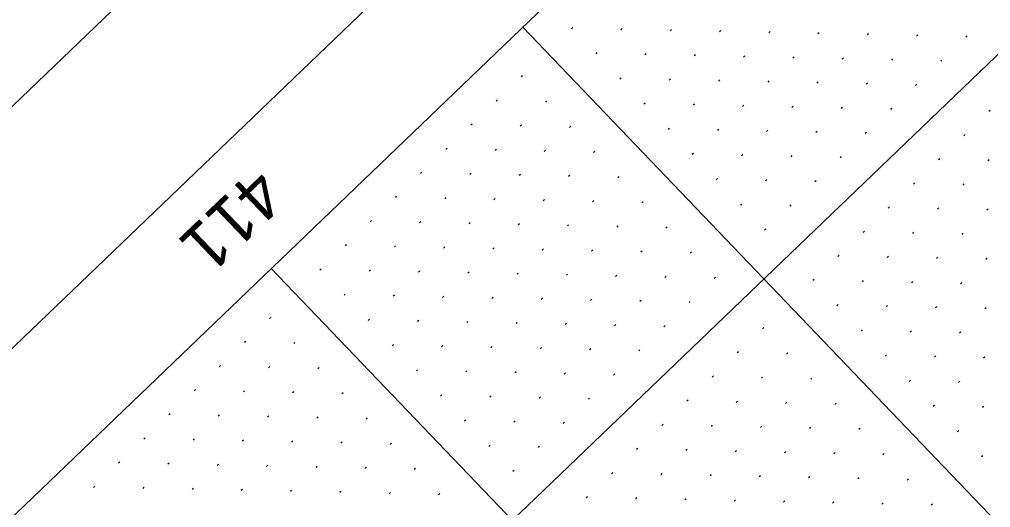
# Model space of a CAD drawing. Extents: x 2148987 to 2151117, y 142806 to 144993.
# Drawn here: x 2149731 to 2149870.3, y 144245 to 144315 of the extents above; entities that cross this region are included whole.
import ezdxf

# ---------------------------------------------------------------- set-up
doc = ezdxf.new("R2010")
doc.units = 0
for name, color, linetype in [('BASELINE', 7, 'Continuous'), ('PR_PIER_PH3', 7, 'Continuous'), ('PR_Road_Concrete', 7, 'Continuous'), ('SHT_Profile_Grid_Minor', 7, 'Continuous'), ('Wall D Bore Txt', 7, 'Continuous')]:
    doc.layers.add(name, color=color, linetype=linetype)

msp = doc.modelspace()

# ---------------------------------------------------------------- linework, layer by layer
at = {"layer": 'BASELINE'}
msp.add_lwpolyline([(2151029.45, 144024.32), (2149802.07, 142848.08), (2149040.98, 143642.27), (2150268.36, 144818.51)], close=True, dxfattribs=at)
at = {"layer": 'PR_PIER_PH3'}
for p, q in [((2150261.97, 144684.26), (2149124.83, 143594.52)), ((2149803.2, 144313.87), (2150124.94, 143978.15)), ((2149767.1, 144279.28), (2150113.05, 143918.28))]:
    msp.add_line(p, q, dxfattribs=at)
at = {"layer": 'PR_Road_Concrete'}
msp.add_line((2150227.37, 144720.36), (2149279.76, 143812.24), dxfattribs=at)
msp.add_lwpolyline([(2150941.76, 143974.91), (2149804.63, 142885.16), (2149078.13, 143643.25), (2150215.26, 144733)], close=True, dxfattribs=at)
at = {"layer": 'SHT_Profile_Grid_Minor'}
for p, q in [((2149810.36, 144313.81), (2149810.18, 144313.63)), ((2149817.43, 144313.66), (2149817.25, 144313.48)), ((2149824.5, 144313.51), (2149824.32, 144313.33)), ((2149831.57, 144313.36), (2149831.39, 144313.18)), ((2149838.64, 144313.21), (2149838.46, 144313.03)), ((2149845.71, 144313.05), (2149845.53, 144312.88)), ((2149852.78, 144312.9), (2149852.6, 144312.73)), ((2149859.85, 144312.75), (2149859.67, 144312.58)), ((2149866.92, 144312.6), (2149866.74, 144312.43)), ((2149813.82, 144310.2), (2149813.64, 144310.02)), ((2149820.89, 144310.05), (2149820.71, 144309.87)), ((2149827.96, 144309.9), (2149827.78, 144309.72)), ((2149835.03, 144309.75), (2149834.85, 144309.57)), ((2149842.1, 144309.6), (2149841.92, 144309.42)), ((2149849.17, 144309.44), (2149848.99, 144309.27)), ((2149856.24, 144309.29), (2149856.06, 144309.12)), ((2149863.31, 144309.14), (2149863.13, 144308.97)), ((2149803.14, 144306.89), (2149802.96, 144306.71)), ((2149817.28, 144306.59), (2149817.1, 144306.41)), ((2149824.35, 144306.44), (2149824.17, 144306.26)), ((2149831.42, 144306.29), (2149831.24, 144306.11)), ((2149838.49, 144306.14), (2149838.31, 144305.96)), ((2149845.56, 144305.99), (2149845.38, 144305.81)), ((2149852.63, 144305.83), (2149852.45, 144305.66)), ((2149859.7, 144305.68), (2149859.52, 144305.51)), ((2149799.53, 144303.43), (2149799.35, 144303.26)), ((2149806.6, 144303.28), (2149806.42, 144303.1)), ((2149820.74, 144302.98), (2149820.56, 144302.8)), ((2149827.81, 144302.83), (2149827.63, 144302.65)), ((2149834.88, 144302.68), (2149834.7, 144302.5)), ((2149841.95, 144302.53), (2149841.77, 144302.35)), ((2149849.02, 144302.38), (2149848.84, 144302.2)), ((2149856.09, 144302.22), (2149855.91, 144302.05)), ((2149870.23, 144301.92), (2149870.05, 144301.75)), ((2149795.92, 144299.97), (2149795.74, 144299.8)), ((2149802.99, 144299.82), (2149802.81, 144299.65)), ((2149810.06, 144299.67), (2149809.88, 144299.49)), ((2149824.2, 144299.37), (2149824.02, 144299.19)), ((2149831.27, 144299.22), (2149831.09, 144299.04)), ((2149838.34, 144299.07), (2149838.16, 144298.89)), ((2149845.41, 144298.92), (2149845.23, 144298.74)), ((2149852.48, 144298.77), (2149852.3, 144298.59)), ((2149866.62, 144298.46), (2149866.44, 144298.29)), ((2149792.31, 144296.51), (2149792.13, 144296.34)), ((2149799.38, 144296.36), (2149799.2, 144296.19)), ((2149806.45, 144296.21), (2149806.27, 144296.04)), ((2149813.52, 144296.06), (2149813.34, 144295.88)), ((2149827.66, 144295.76), (2149827.48, 144295.58)), ((2149834.73, 144295.61), (2149834.55, 144295.43)), ((2149841.8, 144295.46), (2149841.62, 144295.28)), ((2149848.87, 144295.31), (2149848.69, 144295.13)), ((2149863.01, 144295), (2149862.83, 144294.83)), ((2149870.08, 144294.85), (2149869.9, 144294.68)), ((2149788.7, 144293.05), (2149788.52, 144292.88)), ((2149795.77, 144292.9), (2149795.59, 144292.73)), ((2149802.84, 144292.75), (2149802.66, 144292.58)), ((2149809.91, 144292.6), (2149809.73, 144292.43)), ((2149816.98, 144292.45), (2149816.8, 144292.27)), ((2149831.12, 144292.15), (2149830.94, 144291.97)), ((2149838.19, 144292), (2149838.01, 144291.82)), ((2149845.26, 144291.85), (2149845.08, 144291.67)), ((2149859.4, 144291.55), (2149859.22, 144291.37)), ((2149866.47, 144291.39), (2149866.29, 144291.22)), ((2149785.09, 144289.59), (2149784.91, 144289.42)), ((2149792.16, 144289.44), (2149791.98, 144289.27)), ((2149799.23, 144289.29), (2149799.05, 144289.12)), ((2149806.3, 144289.14), (2149806.12, 144288.97)), ((2149813.37, 144288.99), (2149813.19, 144288.82)), ((2149820.44, 144288.84), (2149820.26, 144288.66)), ((2149834.58, 144288.54), (2149834.4, 144288.36)), ((2149841.65, 144288.39), (2149841.47, 144288.21)), ((2149855.79, 144288.09), (2149855.61, 144287.91)), ((2149862.86, 144287.94), (2149862.68, 144287.76)), ((2149869.93, 144287.78), (2149869.75, 144287.61)), ((2149781.48, 144286.13), (2149781.3, 144285.96)), ((2149788.55, 144285.98), (2149788.37, 144285.81)), ((2149795.62, 144285.83), (2149795.44, 144285.66)), ((2149802.69, 144285.68), (2149802.51, 144285.51)), ((2149809.76, 144285.53), (2149809.58, 144285.36)), ((2149816.83, 144285.38), (2149816.65, 144285.21)), ((2149823.9, 144285.23), (2149823.72, 144285.06)), ((2149838.04, 144284.93), (2149837.86, 144284.75)), ((2149852.18, 144284.63), (2149852, 144284.45)), ((2149859.25, 144284.48), (2149859.07, 144284.3)), ((2149866.32, 144284.33), (2149866.14, 144284.15)), ((2149777.87, 144282.67), (2149777.69, 144282.5)), ((2149784.94, 144282.52), (2149784.76, 144282.35)), ((2149792.01, 144282.37), (2149791.83, 144282.2)), ((2149799.08, 144282.22), (2149798.9, 144282.05)), ((2149806.15, 144282.07), (2149805.97, 144281.9)), ((2149813.22, 144281.92), (2149813.04, 144281.75)), ((2149820.29, 144281.77), (2149820.11, 144281.6)), ((2149827.36, 144281.62), (2149827.18, 144281.45)), ((2149848.57, 144281.17), (2149848.39, 144280.99)), ((2149855.64, 144281.02), (2149855.46, 144280.84)), ((2149862.71, 144280.87), (2149862.53, 144280.69)), ((2149869.78, 144280.72), (2149869.6, 144280.54)), ((2149774.26, 144279.21), (2149774.08, 144279.04)), ((2149781.33, 144279.06), (2149781.15, 144278.89)), ((2149788.4, 144278.91), (2149788.22, 144278.74)), ((2149795.47, 144278.76), (2149795.29, 144278.59)), ((2149802.54, 144278.61), (2149802.36, 144278.44)), ((2149809.61, 144278.46), (2149809.43, 144278.29)), ((2149816.68, 144278.31), (2149816.5, 144278.14)), ((2149823.75, 144278.16), (2149823.57, 144277.99)), ((2149830.82, 144278.01), (2149830.64, 144277.84)), ((2149844.96, 144277.71), (2149844.78, 144277.53)), ((2149852.03, 144277.56), (2149851.85, 144277.38)), ((2149859.1, 144277.41), (2149858.92, 144277.23)), ((2149866.17, 144277.26), (2149865.99, 144277.08)), ((2149777.72, 144275.6), (2149777.54, 144275.43)), ((2149784.79, 144275.45), (2149784.61, 144275.28)), ((2149791.86, 144275.3), (2149791.68, 144275.13)), ((2149798.93, 144275.15), (2149798.75, 144274.98)), ((2149806, 144275), (2149805.82, 144274.83)), ((2149813.07, 144274.85), (2149812.89, 144274.68)), ((2149820.14, 144274.7), (2149819.96, 144274.53)), ((2149827.21, 144274.55), (2149827.03, 144274.38)), ((2149848.42, 144274.1), (2149848.24, 144273.92)), ((2149855.49, 144273.95), (2149855.31, 144273.77)), ((2149862.56, 144273.8), (2149862.38, 144273.62)), ((2149869.63, 144273.65), (2149869.44, 144273.47)), ((2149767.04, 144272.29), (2149766.86, 144272.12)), ((2149781.18, 144271.99), (2149781, 144271.82)), ((2149788.25, 144271.84), (2149788.07, 144271.67)), ((2149795.32, 144271.69), (2149795.14, 144271.52)), ((2149802.39, 144271.54), (2149802.21, 144271.37)), ((2149809.46, 144271.39), (2149809.28, 144271.22)), ((2149816.53, 144271.24), (2149816.35, 144271.07)), ((2149823.6, 144271.09), (2149823.42, 144270.92)), ((2149837.74, 144270.79), (2149837.56, 144270.62)), ((2149851.88, 144270.49), (2149851.7, 144270.31)), ((2149858.95, 144270.34), (2149858.77, 144270.16)), ((2149866.02, 144270.19), (2149865.83, 144270.01)), ((2149763.43, 144268.83), (2149763.25, 144268.66)), ((2149770.5, 144268.68), (2149770.32, 144268.51)), ((2149784.64, 144268.38), (2149784.46, 144268.21)), ((2149791.71, 144268.23), (2149791.53, 144268.06)), ((2149798.78, 144268.08), (2149798.6, 144267.91)), ((2149805.85, 144267.93), (2149805.67, 144267.76)), ((2149812.92, 144267.78), (2149812.74, 144267.61)), ((2149819.99, 144267.63), (2149819.81, 144267.46)), ((2149834.13, 144267.33), (2149833.95, 144267.16)), ((2149841.2, 144267.18), (2149841.02, 144267.01)), ((2149855.34, 144266.88), (2149855.16, 144266.7)), ((2149862.41, 144266.73), (2149862.22, 144266.55)), ((2149869.47, 144266.58), (2149869.29, 144266.4)), ((2149759.82, 144265.37), (2149759.64, 144265.2)), ((2149766.89, 144265.22), (2149766.71, 144265.05)), ((2149773.96, 144265.07), (2149773.78, 144264.9)), ((2149788.1, 144264.77), (2149787.92, 144264.6)), ((2149795.17, 144264.62), (2149794.99, 144264.45)), ((2149802.24, 144264.47), (2149802.06, 144264.3)), ((2149809.31, 144264.32), (2149809.13, 144264.15)), ((2149816.38, 144264.17), (2149816.2, 144264)), ((2149830.52, 144263.87), (2149830.34, 144263.7)), ((2149837.59, 144263.72), (2149837.41, 144263.55)), ((2149844.66, 144263.57), (2149844.48, 144263.4)), ((2149858.8, 144263.27), (2149858.62, 144263.09)), ((2149865.86, 144263.12), (2149865.68, 144262.94)), ((2149756.21, 144261.91), (2149756.03, 144261.74)), ((2149763.28, 144261.76), (2149763.1, 144261.59)), ((2149770.35, 144261.61), (2149770.17, 144261.44)), ((2149777.42, 144261.46), (2149777.24, 144261.29)), ((2149791.56, 144261.16), (2149791.38, 144260.99)), ((2149798.63, 144261.01), (2149798.45, 144260.84)), ((2149805.7, 144260.86), (2149805.52, 144260.69)), ((2149812.77, 144260.71), (2149812.59, 144260.54)), ((2149826.91, 144260.41), (2149826.73, 144260.24)), ((2149833.98, 144260.26), (2149833.8, 144260.09)), ((2149841.05, 144260.11), (2149840.87, 144259.94)), ((2149848.12, 144259.96), (2149847.94, 144259.79)), ((2149862.26, 144259.66), (2149862.07, 144259.48)), ((2149869.32, 144259.51), (2149869.14, 144259.33)), ((2149752.6, 144258.45), (2149752.42, 144258.28)), ((2149759.67, 144258.3), (2149759.49, 144258.13)), ((2149766.74, 144258.15), (2149766.56, 144257.98)), ((2149773.81, 144258), (2149773.63, 144257.83)), ((2149780.88, 144257.85), (2149780.7, 144257.68)), ((2149795.02, 144257.55), (2149794.84, 144257.38)), ((2149802.09, 144257.4), (2149801.91, 144257.23)), ((2149809.16, 144257.25), (2149808.98, 144257.08)), ((2149823.3, 144256.95), (2149823.12, 144256.78)), ((2149830.37, 144256.8), (2149830.19, 144256.63)), ((2149837.44, 144256.65), (2149837.26, 144256.48)), ((2149844.51, 144256.5), (2149844.33, 144256.33)), ((2149851.58, 144256.35), (2149851.4, 144256.18)), ((2149865.71, 144256.05), (2149865.53, 144255.87)), ((2149748.99, 144254.99), (2149748.81, 144254.82)), ((2149756.06, 144254.84), (2149755.88, 144254.67)), ((2149763.13, 144254.69), (2149762.95, 144254.52)), ((2149770.2, 144254.54), (2149770.02, 144254.37)), ((2149777.27, 144254.39), (2149777.09, 144254.22)), ((2149784.34, 144254.24), (2149784.16, 144254.07)), ((2149798.48, 144253.94), (2149798.3, 144253.77)), ((2149805.55, 144253.79), (2149805.37, 144253.62)), ((2149819.69, 144253.49), (2149819.51, 144253.32)), ((2149826.76, 144253.34), (2149826.58, 144253.17)), ((2149833.83, 144253.19), (2149833.65, 144253.02)), ((2149840.9, 144253.04), (2149840.72, 144252.87)), ((2149847.97, 144252.89), (2149847.79, 144252.72)), ((2149855.04, 144252.74), (2149854.85, 144252.57)), ((2149869.17, 144252.44), (2149868.99, 144252.26)), ((2149745.38, 144251.54), (2149745.2, 144251.36)), ((2149752.45, 144251.39), (2149752.27, 144251.21)), ((2149759.52, 144251.23), (2149759.34, 144251.06)), ((2149766.59, 144251.08), (2149766.41, 144250.91)), ((2149773.66, 144250.93), (2149773.48, 144250.76)), ((2149780.73, 144250.78), (2149780.55, 144250.61)), ((2149787.8, 144250.63), (2149787.62, 144250.46)), ((2149801.94, 144250.33), (2149801.76, 144250.16)), ((2149816.08, 144250.03), (2149815.9, 144249.86)), ((2149823.15, 144249.88), (2149822.97, 144249.71)), ((2149830.22, 144249.73), (2149830.04, 144249.56)), ((2149837.29, 144249.58), (2149837.11, 144249.41)), ((2149844.36, 144249.43), (2149844.18, 144249.26)), ((2149851.43, 144249.28), (2149851.24, 144249.11)), ((2149858.49, 144249.13), (2149858.31, 144248.96)), ((2149741.77, 144248.08), (2149741.59, 144247.9)), ((2149748.84, 144247.93), (2149748.66, 144247.75)), ((2149755.91, 144247.78), (2149755.73, 144247.6)), ((2149762.98, 144247.62), (2149762.8, 144247.45)), ((2149770.05, 144247.47), (2149769.87, 144247.3)), ((2149777.12, 144247.32), (2149776.94, 144247.15)), ((2149784.19, 144247.17), (2149784.01, 144247)), ((2149791.26, 144247.02), (2149791.08, 144246.85)), ((2149812.47, 144246.57), (2149812.29, 144246.4)), ((2149819.54, 144246.42), (2149819.36, 144246.25)), ((2149826.61, 144246.27), (2149826.43, 144246.1)), ((2149833.68, 144246.12), (2149833.5, 144245.95)), ((2149840.75, 144245.97), (2149840.57, 144245.8)), ((2149847.82, 144245.82), (2149847.63, 144245.65)), ((2149854.88, 144245.67), (2149854.7, 144245.5)), ((2149861.95, 144245.52), (2149861.77, 144245.35))]:
    msp.add_line(p, q, dxfattribs=at)

# ---------------------------------------------------------------- texts
at = {"layer": 'Wall D Bore Txt'}
msp.add_text('411', height=7, rotation=223.7809, dxfattribs=at).set_placement((2149764.79, 144294.02))

doc.saveas('drawing.dxf')
